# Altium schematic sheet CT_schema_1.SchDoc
size 501 x 451 mm
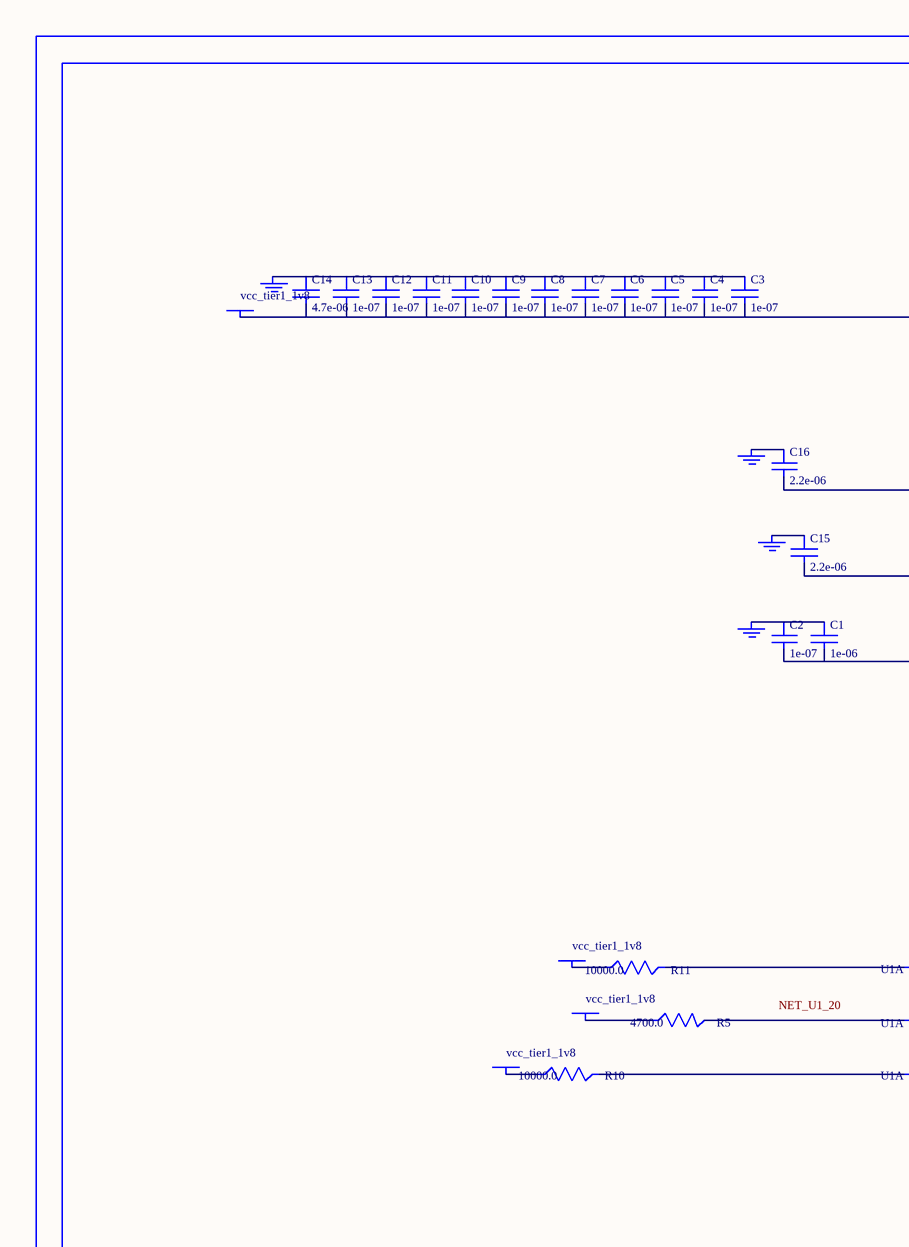
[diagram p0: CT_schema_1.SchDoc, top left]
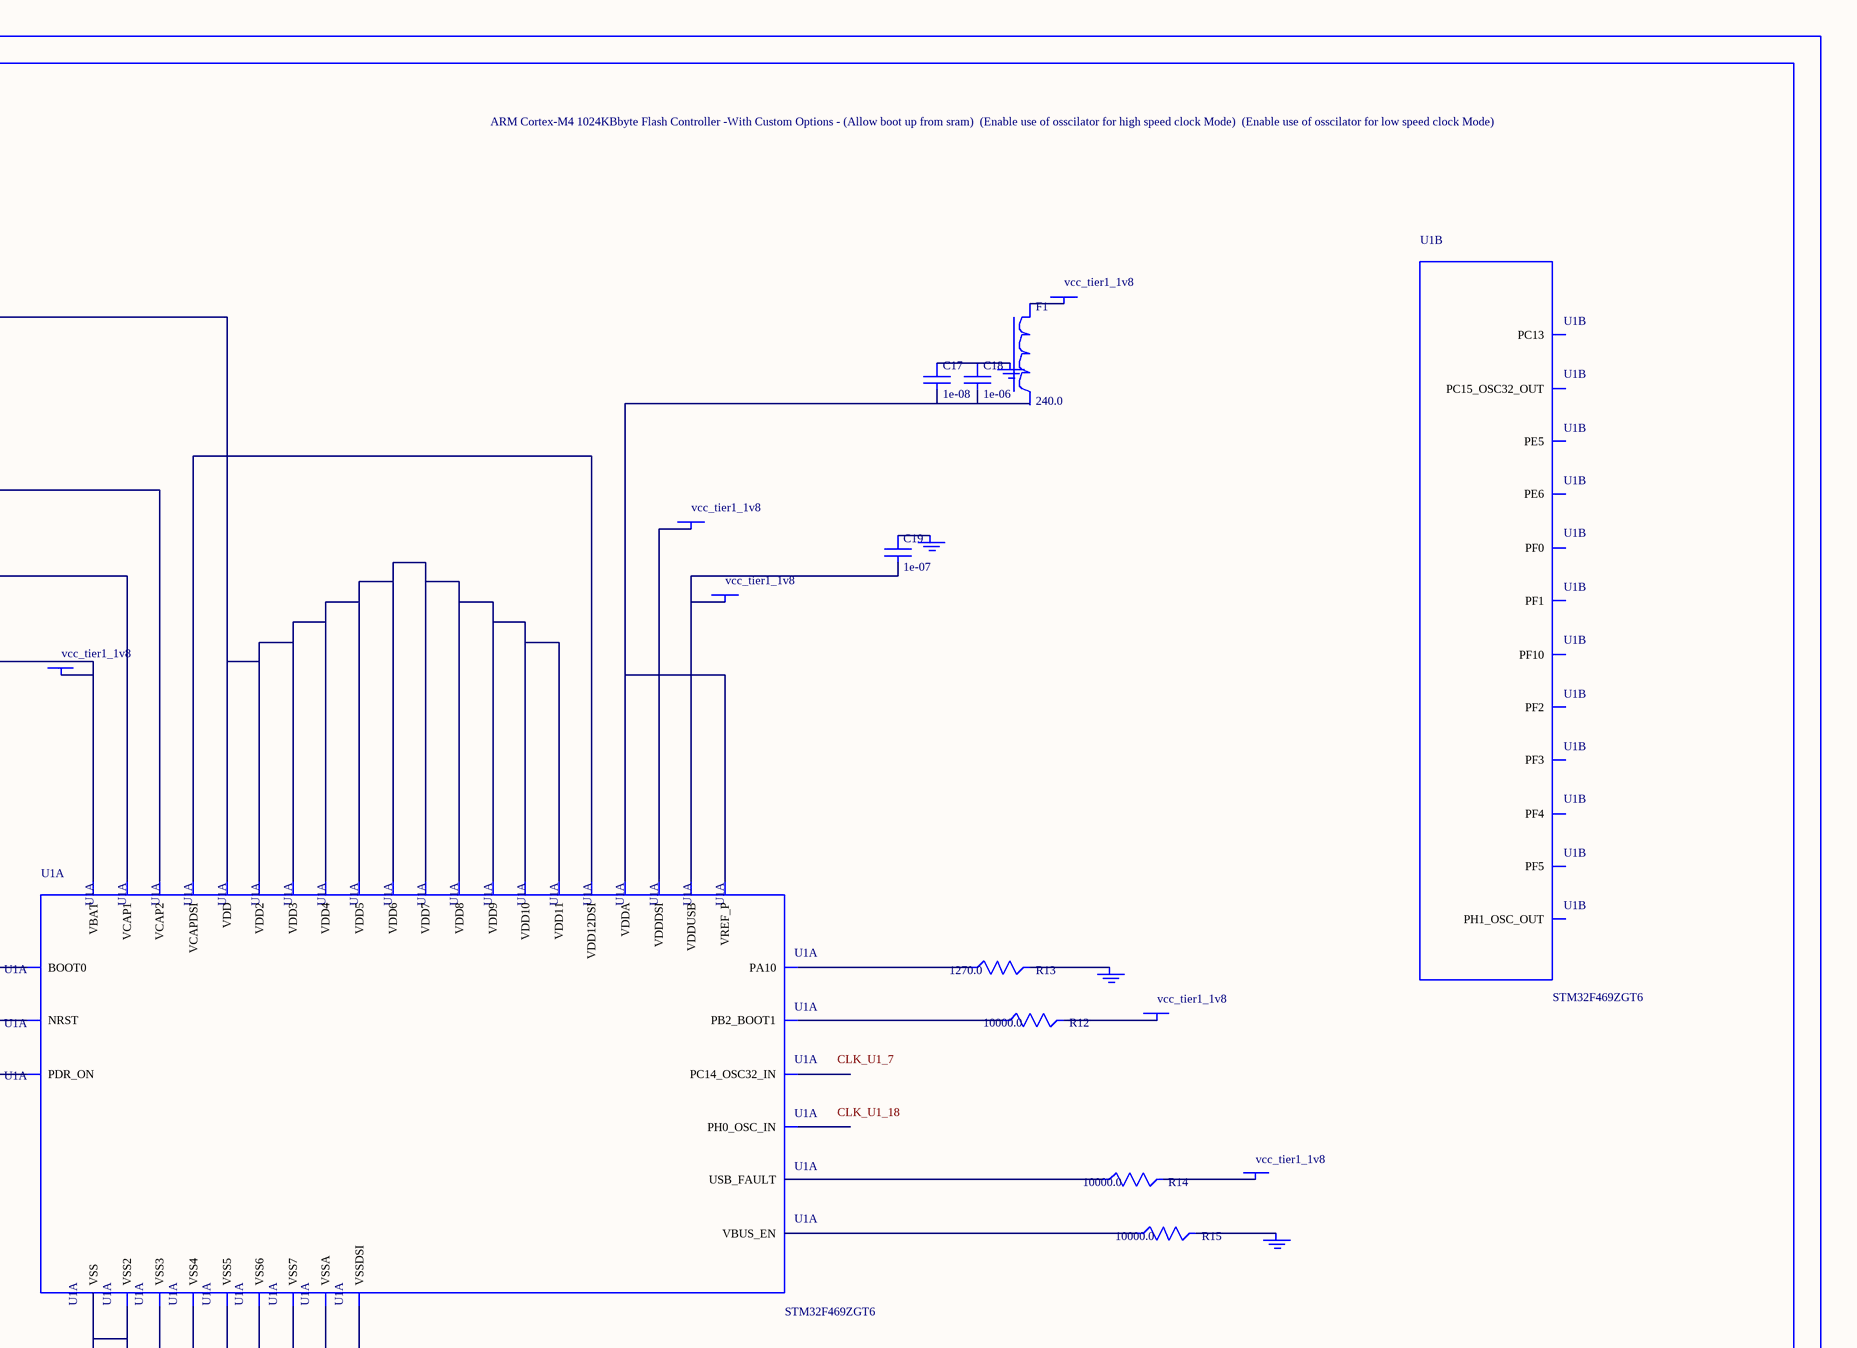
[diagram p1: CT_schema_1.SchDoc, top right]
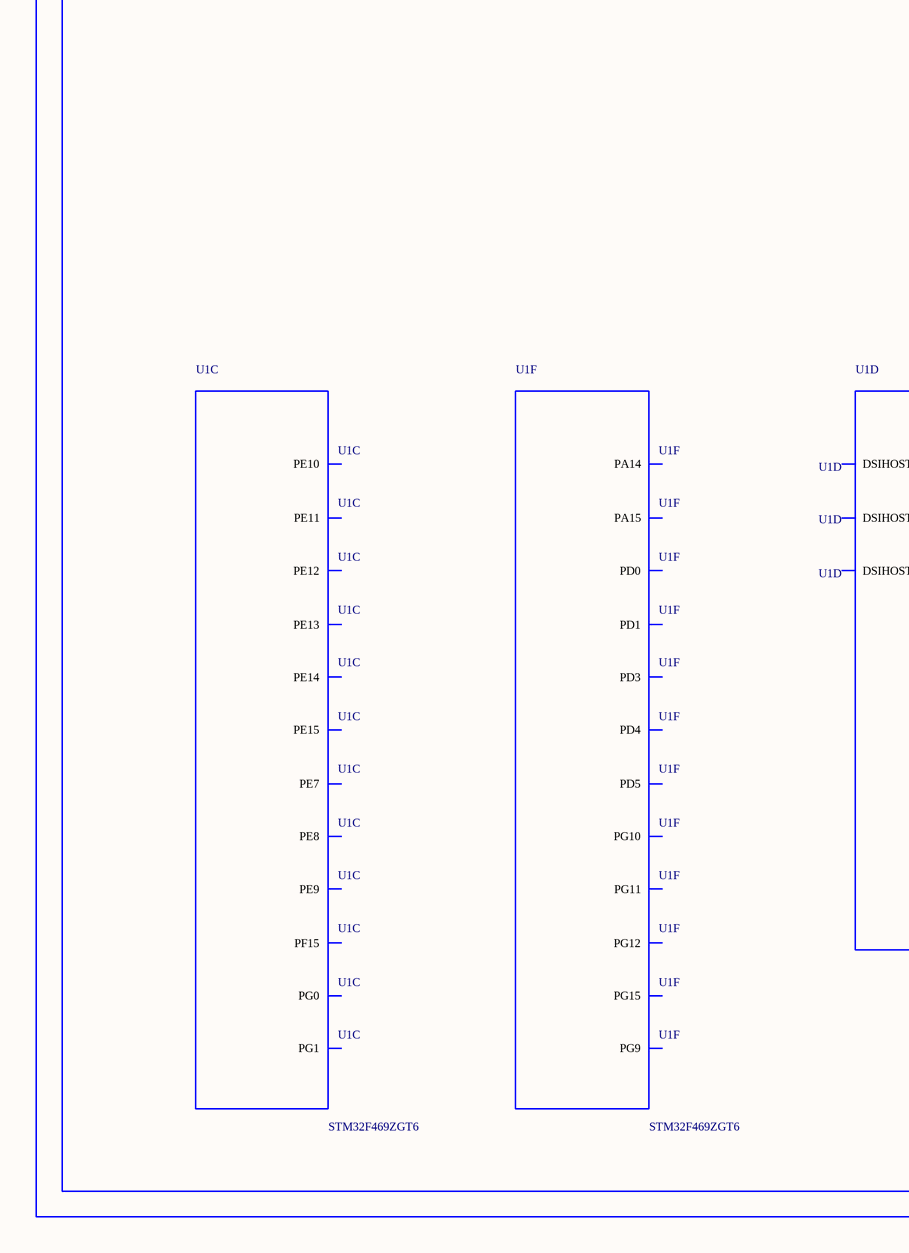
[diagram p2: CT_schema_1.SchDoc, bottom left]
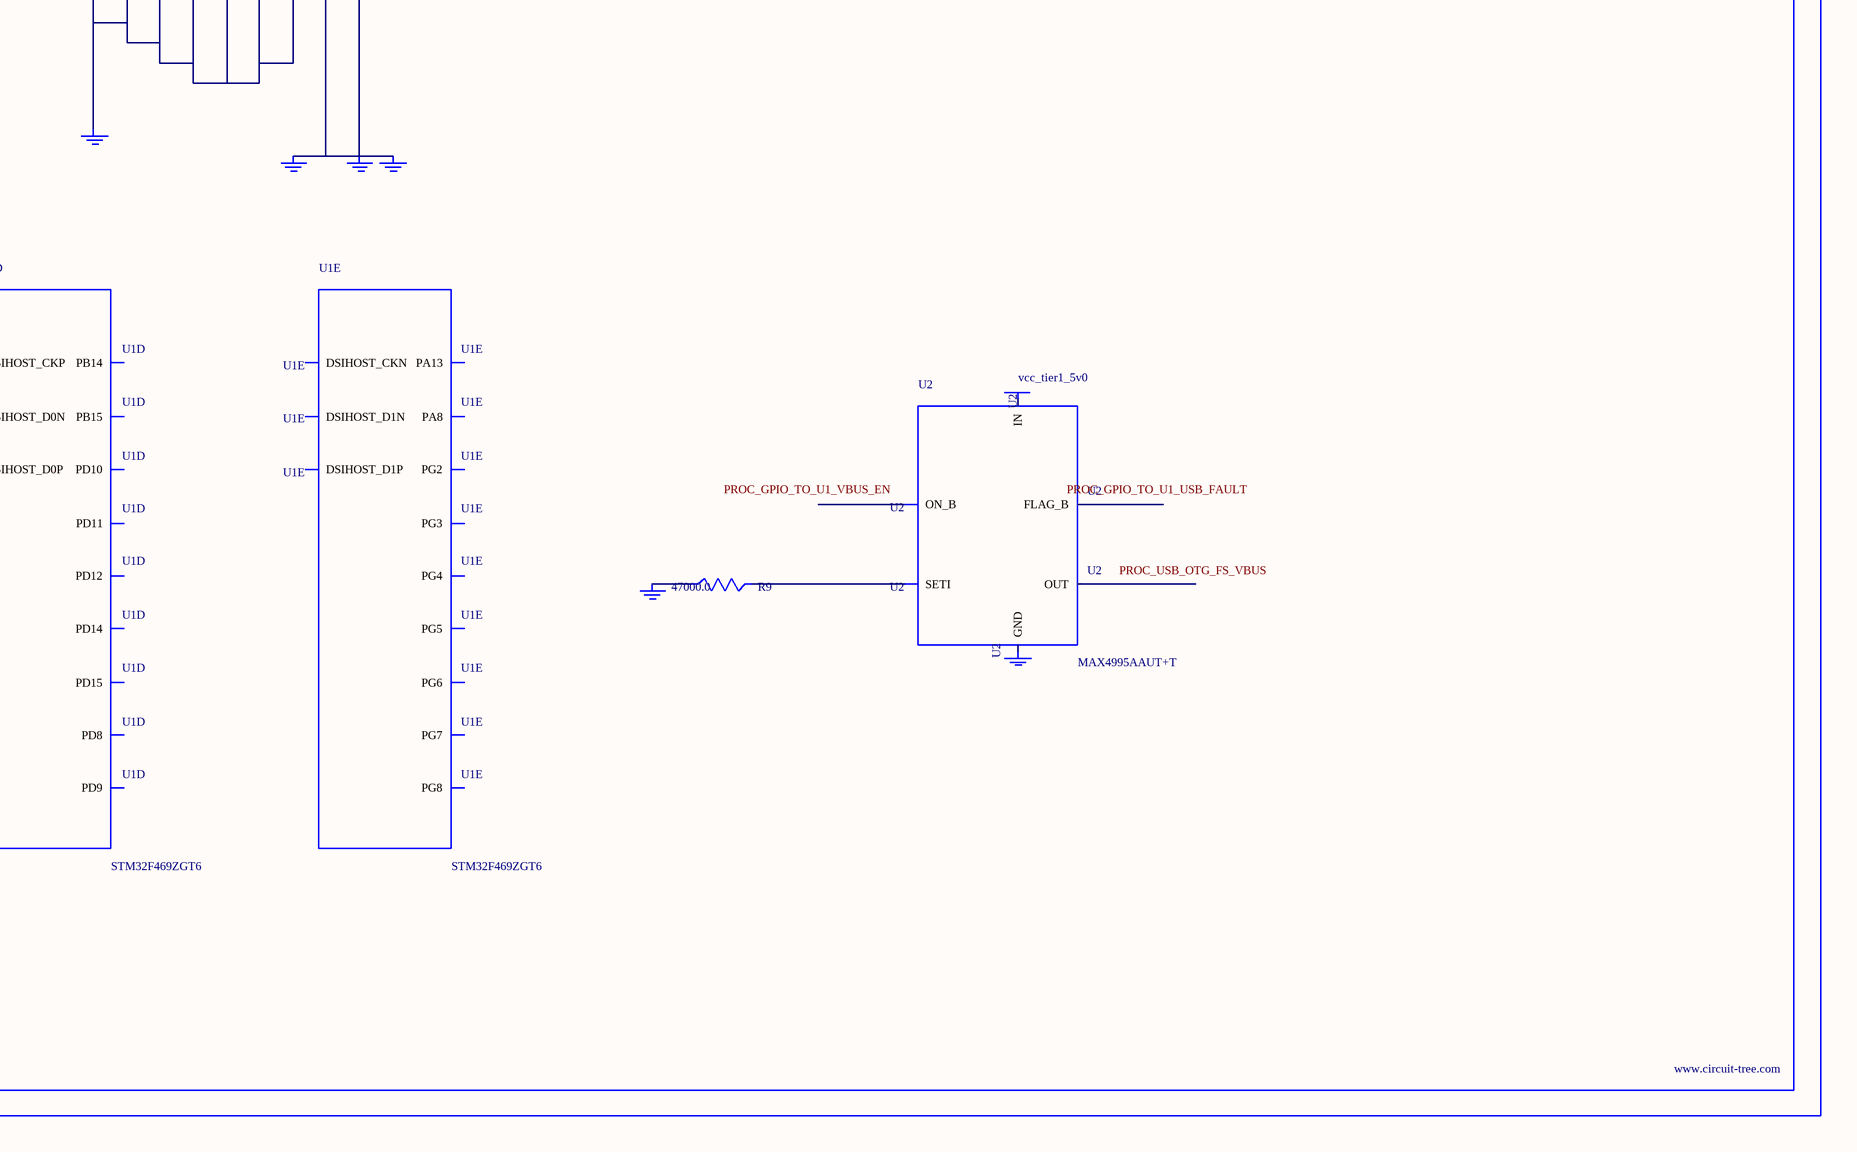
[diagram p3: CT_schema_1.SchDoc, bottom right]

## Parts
BORDER0  (no value)
C1  1e-06  [C0603]
C2  1e-07  [C0603]
C3  1e-07  [C0603]
C4  1e-07  [C0603]
C5  1e-07  [C0603]
C6  1e-07  [C0603]
C7  1e-07  [C0603]
C8  1e-07  [C0603]
C9  1e-07  [C0603]
C10  1e-07  [C0603]
C11  1e-07  [C0603]
C12  1e-07  [C0603]
C13  1e-07  [C0603]
C14  4.7e-06  [C0603]
C15  2.2e-06  [C0603]
C16  2.2e-06  [C0603]
C17  1e-08  [C0603]
C18  1e-06  [C0603]
C19  1e-07  [C0603]
F1  240.0  [L0603]
GND_INSTANCE_0_0  (no value)
GND_INSTANCE_0_1  (no value)
GND_INSTANCE_0_2  (no value)
GND_INSTANCE_0_3  (no value)
GND_INSTANCE_0_4  (no value)
GND_INSTANCE_0_5  (no value)
GND_INSTANCE_0_6  (no value)
GND_INSTANCE_0_7  (no value)
GND_INSTANCE_0_8  (no value)
GND_INSTANCE_0_9  (no value)
GND_INSTANCE_0_10  (no value)
GND_INSTANCE_0_11  (no value)
GND_INSTANCE_0_12  (no value)
GND_INSTANCE_0_13  (no value)
POWER_INSTANCE_0_0  vcc_tier1_1v8
POWER_INSTANCE_0_1  vcc_tier1_1v8
POWER_INSTANCE_0_2  vcc_tier1_1v8
POWER_INSTANCE_0_3  vcc_tier1_1v8
POWER_INSTANCE_0_4  vcc_tier1_1v8
POWER_INSTANCE_0_5  vcc_tier1_1v8
POWER_INSTANCE_0_6  vcc_tier1_1v8
POWER_INSTANCE_0_7  vcc_tier1_1v8
POWER_INSTANCE_0_8  vcc_tier1_1v8
POWER_INSTANCE_0_9  vcc_tier1_1v8
POWER_INSTANCE_0_10  vcc_tier1_5v0
R5  4700.0  [R0603]
R9  47000.0  [R0603]
R10  10000.0  [R0603]
R11  10000.0  [R0603]
R12  10000.0  [R0603]
R13  1270.0  [R0603]
R14  10000.0  [R0603]
R15  10000.0  [R0603]
U1  STM32F469ZGT6  [LQFP144]  (parts A,B,C,D,E,F of 12)
U2  MAX4995AAUT+T  [SOT-23-6]

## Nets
NetC1_1: C1.1 C2.1 GND_INSTANCE_0_1.0(GND)
NetC1_2: C1.2 C2.2 POWER_INSTANCE_0_1.0(PWR) U1.5(VBAT)
NetC3_1: C3.1 C4.1 C5.1 C6.1 C7.1 C8.1 C9.1 C10.1 C11.1 C12.1 C13.1 C14.1 GND_INSTANCE_0_2.0(GND)
NetC3_2: C3.2 C4.2 C5.2 C6.2 C7.2 C8.2 C9.2 C10.2 C11.2 C12.2 C13.2 C14.2 POWER_INSTANCE_0_2.0(PWR) U1.16(VDD) U1.25(VDD2) U1.34(VDD3) U1.46(VDD4) U1.56(VDD5) U1.66(VDD6) U1.77(VDD7) U1.110(VDD8) U1.123(VDD9) U1.130(VDD10) U1.143(VDD11)
NetC15_1: C15.1 GND_INSTANCE_0_5.0(GND)
NetC15_2: C15.2 U1.65(VCAP1)
NetC16_1: C16.1 GND_INSTANCE_0_10.0(GND)
NetC16_2: C16.2 U1.108(VCAP2)
NetC17_1: C17.1 C18.1 GND_INSTANCE_0_4.0(GND)
NetC17_2: C17.2 C18.2 U1.27(VREF_P) U1.28(VDDA)
NetC19_1: C19.1 GND_INSTANCE_0_8.0(GND)
NetC19_2: C19.2 POWER_INSTANCE_0_6.0(PWR) U1.97(VDDUSB)
NetF1_1: F1.1 POWER_INSTANCE_0_3.0(PWR)
NetGND_INSTANCE_0_0_0: GND_INSTANCE_0_0.0(GND) R15.2
NetGND_INSTANCE_0_3_0: GND_INSTANCE_0_3.0(GND) GND_INSTANCE_0_6.0(GND) GND_INSTANCE_0_7.0(GND) U1.26(VSSA) U1.84(VSSDSI)
NetGND_INSTANCE_0_9_0: GND_INSTANCE_0_9.0(GND) R13.2
NetGND_INSTANCE_0_11_0: GND_INSTANCE_0_11.0(GND) U1.15(VSS) U1.33(VSS2) U1.55(VSS3) U1.76(VSS4) U1.109(VSS5) U1.122(VSS6) U1.129(VSS7)
NetGND_INSTANCE_0_12_0: GND_INSTANCE_0_12.0(GND) R9.1
NetPOWER_INSTANCE_0_0_0: POWER_INSTANCE_0_0.0(PWR) R14.2
NetPOWER_INSTANCE_0_4_0: POWER_INSTANCE_0_4.0(PWR) R12.2
NetPOWER_INSTANCE_0_5_0: POWER_INSTANCE_0_5.0(PWR) U1.80(VDDDSI)
NetPOWER_INSTANCE_0_7_0: POWER_INSTANCE_0_7.0(PWR) R11.1
NetPOWER_INSTANCE_0_8_0: POWER_INSTANCE_0_8.0(PWR) R10.1
NetPOWER_INSTANCE_0_9_0: POWER_INSTANCE_0_9.0(PWR) R5.1
NetR5_2: R5.2 U1.20(NRST)
NetR9_2: R9.2 U2.3(SETI)
NetR10_2: R10.2 U1.142(PDR_ON)
NetR11_2: R11.2 U1.137(BOOT0)
NetR12_1: R12.1 U1.43(PB2_BOOT1)
NetR13_1: R13.1 U1.104(PA10)
NetR14_1: R14.1 U1.2(USB_FAULT)
NetR15_1: R15.1 U1.1(VBUS_EN)
NetU1_81: U1.81(VCAPDSI) U1.87(VDD12DSI)

Not connected (* = marked no-connect by the designer): F1 2; GND_INSTANCE_0_13 0(GND); POWER_INSTANCE_0_10 0(PWR); U1 3(PE5) 4(PE6) 6(PC13) 7(PC14_OSC32_IN) 8(PC15_OSC32_OUT) 9(PF0) 10(PF1) 11(PF2) 12(PF3) 13(PF4) 14(PF5) 17(PF10) 18(PH0_OSC_IN) 19(PH1_OSC_OUT) 49(PF15) 50(PG0) 51(PG1) 52(PE7) 53(PE8) 54(PE9) 57(PE10) 58(PE11) 59(PE12) 60(PE13) 61(PE14) 62(PE15) 69(PB14) 70(PB15) 71(PD8) 72(PD9) 73(PD10) 74(PD11) 75(PD12) 78(PD14) 79(PD15) 82(DSIHOST_D0P) 83(DSIHOST_D0N) 85(DSIHOST_CKP) 86(DSIHOST_CKN) 88(DSIHOST_D1P) 89(DSIHOST_D1N) 90(PG2) 91(PG3) 92(PG4) 93(PG5) 94(PG6) 95(PG7) 96(PG8) 102(PA8) 107(PA13) 111(PA14) 112(PA15) 116(PD0) 117(PD1) 119(PD3) 120(PD4) 121(PD5) 125(PG9) 126(PG10) 127(PG11) 128(PG12) 131(PG15); U2 1(OUT) 2(GND) 4(ON_B) 5(IN) 6(FLAG_B)

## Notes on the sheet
- Labels drawn without touching a wire or pin: CLK_U1_7, CLK_U1_18, NET_U1_20, PROC_GPIO_TO_U1_USB_FAULT, PROC_GPIO_TO_U1_VBUS_EN, PROC_USB_OTG_FS_VBUS

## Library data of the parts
BORDER0 = BORDER_PAGE0
C1 C18 = C0603C105K3RACTU
C2-C13 C19 = 06035C104K4Z2A
C14 = GRM188R6YA475KE15D
C15 C16 = C0603C225K8RACTU
C17 = 06035C103K4Z2A
F1 = Z0603C241ASMST
GND_INSTANCE_0_0-GND_INSTANCE_0_13 = GND
POWER_INSTANCE_0_0-POWER_INSTANCE_0_10 = PWR
R5 = RC0603JR-074K7L
R9 = RC0603JR-0747KL
R10-R12 R14 R15 = RC0603JR-0710KL
R13 = RC0603FR-071K27L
